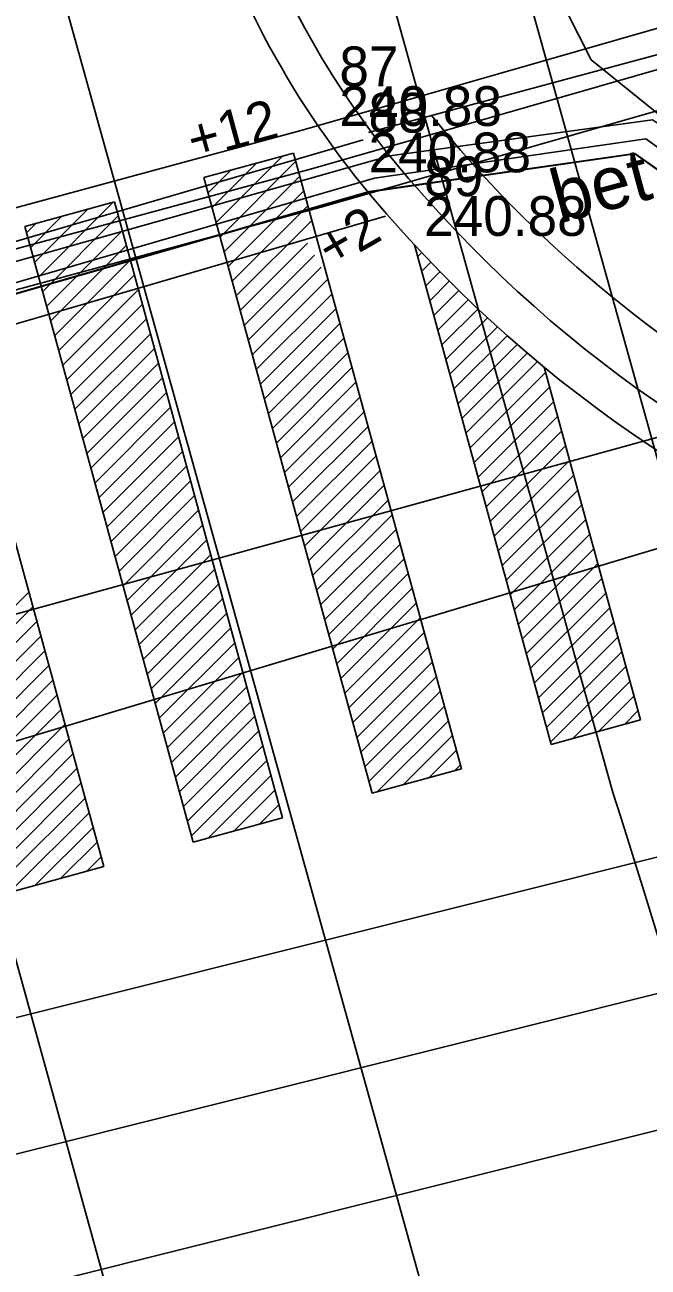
# Model space of a CAD drawing. Extents: x -599432 to -598680, y -1159407 to -1158632.
# Drawn here: x -599023.18 to -599018.48, y -1158883.28 to -1158873.91 of the extents above; entities that cross this region are included whole.
import ezdxf

# ---------------------------------------------------------------- set-up
doc = ezdxf.new("R2010")
doc.units = 0
for name, color, linetype in [('0004 VY - Body podrobné', 7, 'Continuous'), ('0005 VY - Body podrobné - čísla', 7, 'Continuous'), ('0006 VY - Body podrobné - výšky', 7, 'Continuous'), ('0027 ZA - Silnice_cesta zpevněná', 7, 'Continuous'), ('0030 ZA - Chodník', 7, 'Continuous'), ('0031 ZA - Ostatní rozhraní', 7, 'Continuous'), ('0032 TE - Popis povrchu', 7, 'Continuous'), ('0063 ZA - Doprava - vodorovné značení', 7, 'Continuous'), ('0066 ZA - Doprava - DPMB - koleje', 7, 'Continuous'), ('0073 TE - Výška obrubníků a zdí', 7, 'Continuous'), ('0202 PV - MUNI', 7, 'Continuous'), ('0203 PV - MUNI - chránička', 7, 'Continuous'), ('0206 PV - BVK - kanalizace - jednotná', 7, 'Continuous'), ('0302 PV - RWE - NTL', 7, 'Continuous'), ('0304 PV - RWE - STL', 7, 'Continuous'), ('0308 PV - RWE - ochranné pásmo', 7, 'Continuous'), ('0454 PV - O2 - kabel zaměřený', 7, 'Continuous'), ('0455 PV - O2 - kabel nezaměřený', 7, 'Continuous'), ('0530 PV - T-mobile - optické kabely', 7, 'Continuous'), ('0552 PV - NETBOX - vedení', 7, 'Continuous'), ('0552 PV - OT VUT', 7, 'Continuous'), ('0553 PV - NETBOX - chranička', 7, 'Continuous'), ('0652 PV - BKOM - kabely bez rozlišení', 7, 'Continuous'), ('0704 PV - ČD - kabely', 7, 'Continuous')]:
    doc.layers.add(name, color=color, linetype=linetype)

msp = doc.modelspace()

# ---------------------------------------------------------------- linework, layer by layer
at = {"layer": '0004 VY - Body podrobné'}
for p, q in [((-599020.81, -1158874.37), (-599020.81, -1158874.37)), ((-599020.59, -1158874.72), (-599020.59, -1158874.72)), ((-599020.17, -1158875.2), (-599020.17, -1158875.2))]:
    msp.add_line(p, q, dxfattribs=at)
at = {"layer": '0027 ZA - Silnice_cesta zpevněná'}
for centre, radius, start, end in [((-599015.316, -1158870.7954), 6.5545, 197.99199, 222.22107), ((-599012.9494, -1158868.8214), 9.6345, 221.45696, 284.23685)]:
    msp.add_arc(centre, radius, start, end, dxfattribs=at)
at = {"layer": '0030 ZA - Chodník'}
msp.add_line((-599020.59, -1158874.72), (-599012.36, -1158872.5), dxfattribs=at)
at = {"layer": '0031 ZA - Ostatní rozhraní'}
for centre, radius, start, end in [((-599015.316, -1158870.7954), 6.8545, 197.93696, 222.20429), ((-599012.9494, -1158868.8214), 9.1994, 218.84677, 263.74942), ((-599012.9494, -1158868.8214), 9.9345, 221.46846, 284.25776)]:
    msp.add_arc(centre, radius, start, end, dxfattribs=at)
at = {"layer": '0063 ZA - Doprava - vodorovné značení'}
for p, q in [((-599021.1573, -1158874.875), (-599021.8326, -1158875.0595)), ((-599021.7705, -1158875.2867), (-599021.4346, -1158874.9507)), ((-599021.7402, -1158875.3977), (-599021.24, -1158874.8976)), ((-599021.7098, -1158875.5088), (-599021.1399, -1158874.9389)), ((-599019.8876, -1158879.523), (-599021.1573, -1158874.875)), ((-599021.8009, -1158875.1756), (-599021.6292, -1158875.0039)), ((-599021.6795, -1158875.6199), (-599021.1096, -1158875.0499)), ((-599020.5629, -1158879.7075), (-599021.8326, -1158875.0595)), ((-599021.8312, -1158875.0645), (-599021.8238, -1158875.057)), ((-599021.6492, -1158875.731), (-599021.0792, -1158875.161)), ((-599022.5079, -1158875.2439), (-599023.1831, -1158875.4284)), ((-599023.1096, -1158875.6974), (-599022.7119, -1158875.2997)), ((-599023.0793, -1158875.8085), (-599022.5174, -1158875.2465)), ((-599021.2381, -1158879.8919), (-599022.5079, -1158875.2439)), ((-599021.6188, -1158875.842), (-599021.0489, -1158875.2721)), ((-599021.9134, -1158880.0764), (-599023.1831, -1158875.4284)), ((-599023.1703, -1158875.4752), (-599023.1011, -1158875.406)), ((-599023.14, -1158875.5863), (-599022.9065, -1158875.3528)), ((-599023.0489, -1158875.9195), (-599022.479, -1158875.3496)), ((-599021.5885, -1158875.9531), (-599021.0185, -1158875.3832)), ((-599023.0186, -1158876.0306), (-599022.4487, -1158875.4607)), ((-599022.5886, -1158880.2609), (-599023.8584, -1158875.6129)), ((-599022.9883, -1158876.1417), (-599022.4183, -1158875.5717)), ((-599021.5581, -1158876.0642), (-599021.0494, -1158875.5554)), ((-599019.2124, -1158879.3385), (-599020.2427, -1158875.567)), ((-599022.9579, -1158876.2528), (-599022.388, -1158875.6828)), ((-599021.5278, -1158876.1753), (-599020.9978, -1158875.6453)), ((-599020.2184, -1158875.6558), (-599020.1877, -1158875.6251)), ((-599020.188, -1158875.7669), (-599020.1189, -1158875.6978)), ((-599022.9276, -1158876.3638), (-599022.3576, -1158875.7939)), ((-599021.4974, -1158876.2864), (-599020.9463, -1158875.7352)), ((-599020.1577, -1158875.878), (-599020.0491, -1158875.7694)), ((-599021.4671, -1158876.3974), (-599020.8971, -1158875.8275)), ((-599020.1274, -1158875.9891), (-599019.9786, -1158875.8403)), ((-599022.8972, -1158876.4749), (-599022.3273, -1158875.905)), ((-599021.4368, -1158876.5085), (-599020.8668, -1158875.9386)), ((-599020.097, -1158876.1002), (-599019.9081, -1158875.9112)), ((-599020.0667, -1158876.2112), (-599019.836, -1158875.9805)), ((-599022.8669, -1158876.586), (-599022.2969, -1158876.016)), ((-599021.4064, -1158876.6196), (-599020.8365, -1158876.0496)), ((-599020.0363, -1158876.3223), (-599019.7635, -1158876.0494)), ((-599022.8365, -1158876.6971), (-599022.2666, -1158876.1271)), ((-599021.3761, -1158876.7307), (-599020.8061, -1158876.1607)), ((-599020.006, -1158876.4334), (-599019.6909, -1158876.1184)), ((-599022.8062, -1158876.8081), (-599022.2362, -1158876.2382)), ((-599021.3457, -1158876.8417), (-599020.7758, -1158876.2718)), ((-599019.9756, -1158876.5445), (-599019.6164, -1158876.1853)), ((-599019.9453, -1158876.6555), (-599019.5419, -1158876.2522)), ((-599022.7759, -1158876.9192), (-599022.2059, -1158876.3493)), ((-599019.9149, -1158876.7666), (-599019.4671, -1158876.3187)), ((-599022.7455, -1158877.0303), (-599022.1756, -1158876.4604)), ((-599021.3154, -1158876.9528), (-599020.7454, -1158876.3829)), ((-599019.8846, -1158876.8777), (-599019.3905, -1158876.3836)), ((-599019.8543, -1158876.9888), (-599019.314, -1158876.4485)), ((-599021.285, -1158877.0639), (-599020.7151, -1158876.4939)), ((-599019.8239, -1158877.0999), (-599019.254, -1158876.5299)), ((-599018.5371, -1158879.1541), (-599019.2648, -1158876.4902)), ((-599022.7152, -1158877.1414), (-599022.1452, -1158876.5714)), ((-599021.2547, -1158877.175), (-599020.6847, -1158876.605)), ((-599019.7936, -1158877.2109), (-599019.2236, -1158876.641)), ((-599022.6848, -1158877.2525), (-599022.1149, -1158876.6825)), ((-599021.2243, -1158877.2861), (-599020.6544, -1158876.7161)), ((-599022.6545, -1158877.3635), (-599022.0845, -1158876.7936)), ((-599021.194, -1158877.3971), (-599020.624, -1158876.8272)), ((-599019.7632, -1158877.322), (-599019.1933, -1158876.7521)), ((-599022.6241, -1158877.4746), (-599022.0542, -1158876.9047)), ((-599019.7329, -1158877.4331), (-599019.1629, -1158876.8631)), ((-599022.5938, -1158877.5857), (-599022.0238, -1158877.0157)), ((-599021.1637, -1158877.5082), (-599020.5937, -1158876.9383)), ((-599019.7025, -1158877.5442), (-599019.1326, -1158876.9742)), ((-599021.1333, -1158877.6193), (-599020.5634, -1158877.0493)), ((-599019.6722, -1158877.6552), (-599019.1022, -1158877.0853)), ((-599022.5634, -1158877.6968), (-599021.9935, -1158877.1268)), ((-599021.103, -1158877.7304), (-599020.533, -1158877.1604)), ((-599019.6418, -1158877.7663), (-599019.0719, -1158877.1964)), ((-599022.5331, -1158877.8078), (-599021.9632, -1158877.2379)), ((-599021.0726, -1158877.8414), (-599020.5027, -1158877.2715)), ((-599022.5028, -1158877.9189), (-599021.9328, -1158877.349)), ((-599021.0423, -1158877.9525), (-599020.4723, -1158877.3826)), ((-599019.6115, -1158877.8774), (-599019.0416, -1158877.3074)), ((-599022.4724, -1158878.03), (-599021.9025, -1158877.46)), ((-599019.5812, -1158877.9885), (-599019.0112, -1158877.4185)), ((-599022.4421, -1158878.1411), (-599021.8721, -1158877.5711)), ((-599021.0119, -1158878.0636), (-599020.442, -1158877.4936)), ((-599019.5508, -1158878.0995), (-599018.9809, -1158877.5296)), ((-599020.9816, -1158878.1747), (-599020.4116, -1158877.6047)), ((-599019.5205, -1158878.2106), (-599018.9505, -1158877.6407)), ((-599022.4117, -1158878.2522), (-599021.8418, -1158877.6822)), ((-599020.9512, -1158878.2858), (-599020.3813, -1158877.7158)), ((-599019.4901, -1158878.3217), (-599018.9202, -1158877.7518)), ((-599022.3814, -1158878.3632), (-599021.8114, -1158877.7933)), ((-599020.9209, -1158878.3968), (-599020.351, -1158877.8269)), ((-599019.4598, -1158878.4328), (-599018.8898, -1158877.8628)), ((-599022.351, -1158878.4743), (-599021.7811, -1158877.9044)), ((-599020.8906, -1158878.5079), (-599020.3206, -1158877.938)), ((-599022.3207, -1158878.5854), (-599021.7507, -1158878.0154)), ((-599020.8602, -1158878.619), (-599020.2903, -1158878.049)), ((-599019.4294, -1158878.5439), (-599018.8595, -1158877.9739)), ((-599022.2904, -1158878.6965), (-599021.7204, -1158878.1265)), ((-599019.3991, -1158878.6549), (-599018.8291, -1158878.085)), ((-599023.7248, -1158878.7583), (-599023.1548, -1158878.1883)), ((-599022.26, -1158878.8075), (-599021.6901, -1158878.2376)), ((-599020.8299, -1158878.7301), (-599020.2599, -1158878.1601)), ((-599019.3688, -1158878.766), (-599018.7988, -1158878.1961)), ((-599023.6944, -1158878.8693), (-599023.1245, -1158878.2994)), ((-599020.7995, -1158878.8411), (-599020.2296, -1158878.2712)), ((-599019.3384, -1158878.8771), (-599018.7685, -1158878.3071)), ((-599023.6641, -1158878.9804), (-599023.0941, -1158878.4105)), ((-599022.2297, -1158878.9186), (-599021.6597, -1158878.3487)), ((-599020.7692, -1158878.9522), (-599020.1992, -1158878.3823)), ((-599019.3081, -1158878.9882), (-599018.7381, -1158878.4182)), ((-599023.6337, -1158879.0915), (-599023.0638, -1158878.5215)), ((-599022.1993, -1158879.0297), (-599021.6294, -1158878.4597)), ((-599020.7388, -1158879.0633), (-599020.1689, -1158878.4933)), ((-599022.169, -1158879.1408), (-599021.599, -1158878.5708)), ((-599020.7085, -1158879.1744), (-599020.1385, -1158878.6044)), ((-599019.2777, -1158879.0992), (-599018.7078, -1158878.5293)), ((-599023.6034, -1158879.2026), (-599023.0334, -1158878.6326)), ((-599022.1386, -1158879.2518), (-599021.5687, -1158878.6819)), ((-599019.2474, -1158879.2103), (-599018.6774, -1158878.6404)), ((-599023.573, -1158879.3136), (-599023.0031, -1158878.7437)), ((-599022.1083, -1158879.3629), (-599021.5383, -1158878.793)), ((-599020.6782, -1158879.2854), (-599020.1082, -1158878.7155)), ((-599019.217, -1158879.3214), (-599018.6471, -1158878.7514)), ((-599023.5427, -1158879.4247), (-599022.9728, -1158878.8548)), ((-599020.6478, -1158879.3965), (-599020.0779, -1158878.8266)), ((-599019.0478, -1158879.2936), (-599018.6167, -1158878.8625)), ((-599023.5124, -1158879.5358), (-599022.9424, -1158878.9658)), ((-599022.0779, -1158879.474), (-599021.508, -1158878.9041)), ((-599020.6175, -1158879.5076), (-599020.0475, -1158878.9377)), ((-599018.8532, -1158879.2404), (-599018.5864, -1158878.9736)), ((-599023.482, -1158879.6469), (-599022.9121, -1158879.0769)), ((-599022.0476, -1158879.5851), (-599021.4776, -1158879.0151)), ((-599020.5871, -1158879.6187), (-599020.0172, -1158879.0487)), ((-599018.6586, -1158879.1873), (-599018.556, -1158879.0847)), ((-599022.0173, -1158879.6962), (-599021.4473, -1158879.1262)), ((-599020.5238, -1158879.6968), (-599019.9868, -1158879.1598)), ((-599018.5371, -1158879.1541), (-599019.2124, -1158879.3385)), ((-599023.4517, -1158879.758), (-599022.8817, -1158879.188)), ((-599021.9869, -1158879.8072), (-599021.417, -1158879.2373)), ((-599020.3292, -1158879.6436), (-599019.9565, -1158879.2709)), ((-599023.4213, -1158879.869), (-599022.8514, -1158879.2991)), ((-599021.9566, -1158879.9183), (-599021.3866, -1158879.3484)), ((-599023.391, -1158879.9801), (-599022.821, -1158879.4102)), ((-599021.9262, -1158880.0294), (-599021.3563, -1158879.4594)), ((-599020.1347, -1158879.5905), (-599019.9261, -1158879.382)), ((-599023.3606, -1158880.0912), (-599022.7907, -1158879.5212)), ((-599019.8876, -1158879.523), (-599020.5629, -1158879.7075)), ((-599019.9401, -1158879.5373), (-599019.8958, -1158879.493)), ((-599023.3303, -1158880.2023), (-599022.7603, -1158879.6323)), ((-599021.8011, -1158880.0457), (-599021.3259, -1158879.5705)), ((-599023.3, -1158880.3133), (-599022.73, -1158879.7434)), ((-599021.6066, -1158879.9926), (-599021.2956, -1158879.6816)), ((-599021.412, -1158879.9394), (-599021.2652, -1158879.7927)), ((-599023.2696, -1158880.4244), (-599022.6997, -1158879.8545)), ((-599021.2381, -1158879.8919), (-599021.9134, -1158880.0764)), ((-599023.1059, -1158880.4022), (-599022.6693, -1158879.9655)), ((-599022.9114, -1158880.349), (-599022.639, -1158880.0766)), ((-599022.7168, -1158880.2959), (-599022.6086, -1158880.1877)), ((-599022.5886, -1158880.2609), (-599023.2639, -1158880.4453))]:
    msp.add_line(p, q, dxfattribs=at)
at = {"layer": '0066 ZA - Doprava - DPMB - koleje'}
msp.add_line((-599026.9947, -1158867.4391), (-599013.0005, -1158918.0205), dxfattribs=at)
at = {"layer": '0202 PV - MUNI'}
msp.add_lwpolyline([(-599146.6366, -1158922.9878), (-599125.8483, -1158917.7447), (-599099.1764, -1158910.8285), (-599079.1004, -1158904.889), (-599063.7152, -1158899.846), (-599061.634, -1158898.4051), (-599061.0656, -1158896.468), (-599061.7781, -1158890.9687), (-599061.2017, -1158889.9281), (-599056.1907, -1158887.5907), (-599053.9174, -1158887.4786), (-599048.5222, -1158885.3494), (-599047.3855, -1158884.4528), (-599040.0211, -1158881.2029), (-599032.6727, -1158878.6013), (-599020.5455, -1158875.0632), (-599018.4963, -1158874.7671), (-599015.6546, -1158876.8083), (-599014.9422, -1158877.8009)], dxfattribs=at)
at = {"layer": '0203 PV - MUNI - chránička'}
for p, q in [((-599032.7567, -1158878.3133), (-599020.6295, -1158874.7752)), ((-599032.5887, -1158878.8893), (-599020.4615, -1158875.3512))]:
    msp.add_line(p, q, dxfattribs=at)
at = {"layer": '0206 PV - BVK - kanalizace - jednotná'}
msp.add_lwpolyline([(-599032.769, -1158838.166), (-599031.797, -1158841.663), (-599030.578, -1158846.047), (-599029.02, -1158851.655), (-599028.966, -1158851.847), (-599026.936, -1158859.15), (-599023.002, -1158873.304), (-599020.124, -1158883.658), (-599020.103, -1158883.727), (-599020.068, -1158883.807), (-599020.021, -1158883.887), (-599019.966, -1158883.958), (-599019.906, -1158884.02), (-599019.864, -1158884.058), (-599019.825, -1158884.088), (-599019.771, -1158884.124), (-599019.71, -1158884.156), (-599019.666, -1158884.176), (-599019.635, -1158884.189), (-599019.566, -1158884.21), (-599018.079, -1158884.603)], dxfattribs=at)
at = {"layer": '0302 PV - RWE - NTL'}
msp.add_lwpolyline([(-599031.044, -1158884.383), (-598999.16, -1158876.4), (-598995.29, -1158875.42), (-598995.15, -1158875.39), (-598995.04, -1158875.36)], dxfattribs=at)
at = {"layer": '0304 PV - RWE - STL'}
msp.add_lwpolyline([(-599012.11, -1158899.9), (-599012.24, -1158899.43), (-599012.75, -1158897.13), (-599015.27, -1158888.25), (-599015.46, -1158887.31), (-599017.06, -1158881.76), (-599017.557, -1158880.15), (-599017.73, -1158879.59), (-599017.79, -1158879.41), (-599023.8, -1158857.83), (-599030.9921, -1158832.0458)], dxfattribs=at)
at = {"layer": '0308 PV - RWE - ochranné pásmo'}
msp.add_lwpolyline([(-599018.018, -1158882.046), (-599018.512, -1158880.445), (-599018.682, -1158879.896), (-599018.747, -1158879.702), (-599024.763, -1158858.098)], dxfattribs=at)
msp.add_lwpolyline([(-599031.689, -1158883.514), (-599031.287, -1158883.413), (-598999.404, -1158875.43), (-598995.518, -1158874.446), (-598995.387, -1158874.418), (-598995.303, -1158874.395), (-598994.903, -1158874.286), (-598994.184, -1158874.697), (-598994.075, -1158875.097), (-598993.966, -1158875.497), (-598994.377, -1158876.216), (-598994.777, -1158876.325), (-598994.913, -1158876.362), (-598995.062, -1158876.394), (-598998.916, -1158877.37), (-599030.801, -1158885.353), (-599031.203, -1158885.454), (-599031.913, -1158885.028), (-599032.014, -1158884.626), (-599032.115, -1158884.224)], close=True, dxfattribs=at)
at = {"layer": '0454 PV - O2 - kabel zaměřený'}
for points in [[(-599065.99, -1158901.17), (-599063.3, -1158900.18), (-599061.65, -1158898.45), (-599061.04, -1158896.51), (-599061.91, -1158890.95), (-599061.26, -1158889.87), (-599056.07, -1158887.58), (-599053.91, -1158887.47), (-599052.4, -1158886.85), (-599049.09, -1158885.94), (-599048.46, -1158885.4), (-599047.47, -1158884.55), (-599040.18, -1158881.35), (-599032.72, -1158878.67), (-599020.59, -1158875.17), (-599018.58, -1158874.88), (-599016.36, -1158876.44), (-599015.76, -1158876.86), (-599014.99, -1158877.89), (-599012.08, -1158888.14), (-599011.3, -1158889.38), (-599007.9, -1158892.89), (-599006.6, -1158893.35), (-598996.83, -1158890.81)], [(-599032.72, -1158878.67), (-599020.59, -1158875.17)]]:
    msp.add_lwpolyline(points, dxfattribs=at)
at = {"layer": '0455 PV - O2 - kabel nezaměřený'}
msp.add_lwpolyline([(-599011.61, -1158875.82), (-599033.5, -1158882.39)], dxfattribs=at)
at = {"layer": '0530 PV - T-mobile - optické kabely'}
for points in [[(-599018.579, -1158874.878), (-599020.585, -1158875.165)], [(-599015.758, -1158876.853), (-599018.579, -1158874.878)], [(-599020.585, -1158875.165), (-599032.721, -1158878.667)]]:
    msp.add_lwpolyline(points, dxfattribs=at)
at = {"layer": '0552 PV - NETBOX - vedení'}
msp.add_lwpolyline([(-599006.06, -1158869.51), (-599006.06, -1158869.51), (-599007.15, -1158869.17), (-599007.15, -1158869.17), (-599008.89, -1158870.73), (-599009.02, -1158871.08), (-599010.62, -1158871.57), (-599015.34, -1158873.36), (-599021.01, -1158874.99), (-599029.72, -1158877.35), (-599032.35, -1158878.18), (-599038.52, -1158879.88), (-599044.56, -1158881.49), (-599050.4, -1158884.03), (-599052.74, -1158885.29), (-599055.15, -1158886.37), (-599057.94, -1158887.57), (-599060.68, -1158888.43), (-599062.55, -1158889.31)], dxfattribs=at)
at = {"layer": '0552 PV - OT VUT'}
msp.add_lwpolyline([(-599033.7405, -1158881.2436), (-599014.077, -1158875.8253), (-599000.0421, -1158871.6319), (-598993.2337, -1158890.9364), (-598991.5321, -1158891.5418)], dxfattribs=at)
at = {"layer": '0553 PV - NETBOX - chranička'}
msp.add_lwpolyline([(-599015.4348, -1158873.0751), (-599021.0907, -1158874.701), (-599029.8044, -1158877.0621), (-599032.435, -1158877.8922), (-599038.5985, -1158879.5904), (-599044.659, -1158881.2059), (-599050.53, -1158883.7594), (-599053.1483, -1158885.1442), (-599055.2706, -1158886.0953), (-599058.0445, -1158887.2884), (-599060.7893, -1158888.1499), (-599062.6777, -1158889.0386), (-599062.4223, -1158889.5814), (-599060.5707, -1158888.7101), (-599057.8355, -1158887.8516), (-599055.0294, -1158886.6447), (-599052.3317, -1158885.4358), (-599050.27, -1158884.3006), (-599044.461, -1158881.7741), (-599038.4415, -1158880.1696), (-599032.265, -1158878.4678), (-599029.6356, -1158877.6379), (-599020.9293, -1158875.279), (-599015.2452, -1158873.6449)], dxfattribs=at)
at = {"layer": '0652 PV - BKOM - kabely bez rozlišení'}
for points in [[(-599012.374, -1158857.616), (-599013.19, -1158857.86), (-599018.08, -1158859.1), (-599018.5, -1158859.81), (-599016.73, -1158866.41), (-599019.7, -1158871.25), (-599019.95, -1158872.38), (-599019.48, -1158873.04), (-599018.91, -1158874.17), (-599016.73, -1158875.93), (-599015.62, -1158876.75), (-599013.57, -1158877.37), (-599011.16, -1158877.03), (-599007.55, -1158875.71), (-599007.594, -1158874.617)], [(-599069.54, -1158906.27), (-599056.01, -1158902.46), (-599042.94, -1158898.82), (-599036.88, -1158897.21), (-599035.9, -1158896.65), (-599035.19, -1158895.15), (-599033.43, -1158892.94), (-599032.55, -1158892.85), (-599032.38, -1158891.47), (-599031.43, -1158887.7), (-599033.39, -1158880.98), (-599034.34, -1158877.53), (-599034.11, -1158876.42), (-599020.38, -1158872.59), (-599019.95, -1158872.38), (-599019.48, -1158873.04), (-599018.91, -1158874.17), (-599016.73, -1158875.93), (-599015.62, -1158876.75), (-599013.57, -1158877.37), (-599011.16, -1158877.03), (-599007.55, -1158875.71), (-599006.793, -1158874.464)]]:
    msp.add_lwpolyline(points, dxfattribs=at)
at = {"layer": '0704 PV - ČD - kabely'}
msp.add_lwpolyline([(-598961.1998, -1158881.213), (-599006.8409, -1158893.8814), (-599007.9998, -1158893.3892), (-599012.4449, -1158888.2457), (-599014.7944, -1158877.5617), (-599015.5723, -1158876.5616), (-599018.4457, -1158874.6248), (-599020.4301, -1158874.8947), (-599032.7968, -1158878.3872), (-599047.1639, -1158884.134), (-599048.6403, -1158885.0865), (-599049.561, -1158885.3882), (-599050.6564, -1158886.3724), (-599052.3709, -1158886.6423), (-599054.1807, -1158887.3884), (-599056.3556, -1158887.4043), (-599061.2213, -1158889.6983), (-599062.0071, -1158890.8333), (-599061.1578, -1158896.5405), (-599061.8246, -1158898.4296), (-599063.5073, -1158900.1441), (-599114.0221, -1158914.7334)], dxfattribs=at)

# ---------------------------------------------------------------- texts
at = {"layer": '0005 VY - Body podrobné - čísla'}
for s, p in [('87', (-599020.81, -1158874.37)), ('88', (-599020.59, -1158874.72)), ('89', (-599020.17, -1158875.2))]:
    msp.add_text(s, height=0.3, dxfattribs=at).set_placement(p)
at = {"layer": '0006 VY - Body podrobné - výšky'}
for p in [(-599020.81, -1158874.67), (-599020.59, -1158875.02), (-599020.17, -1158875.5)]:
    msp.add_text('240.88', height=0.3, dxfattribs=at).set_placement(p)
at = {"layer": '0032 TE - Popis povrchu'}
msp.add_text('bet.dl.20x20', height=0.4, rotation=15.05548, dxfattribs=at).set_placement((-599019.1474, -1158875.4073))
at = {"layer": '0073 TE - Výška obrubníků a zdí'}
for s, rotation, p in [('+12', 15.18958, (-599021.909, -1158874.9298)), ('+2', 29.82518, (-599020.8689, -1158875.7496))]:
    msp.add_text(s, height=0.3, rotation=rotation, dxfattribs=at).set_placement(p)

doc.saveas('drawing.dxf')
